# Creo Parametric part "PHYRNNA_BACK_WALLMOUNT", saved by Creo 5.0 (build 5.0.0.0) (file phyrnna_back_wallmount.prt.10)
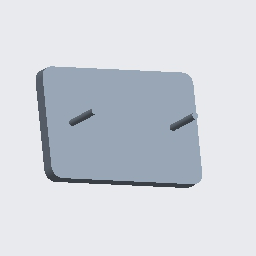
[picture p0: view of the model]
Units: Inch lbm Second (Pro/E Default); INCH, POUND, SECS

Created from: INLBS_PART_SOLID.PRT

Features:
  1. datum plane "RIGHT"
  2. datum plane "TOP"
  3. datum plane "FRONT"
  4. coordinate system
  5. sketch "Sketch 1"
  6. extrusion "Extrude 1"
  7. sketch "Sketch 2"
  8. extrusion "Extrude 2"
  9. sketch "Sketch 1", "A_3"
  10. extruded cut "Extrude 1"
  11. chamfer "Chamfer 1"
  12. sketch "Sketch 2"
  13. extruded cut "Extrude 2"

Other named items: BASE_S, BASE_E, PEG_S, PEG_E, NOTCH_S, NOTCH_E, NOTCH_C, GROOVE_S, GROOVE_E

Surfaces: 14 plane, 6 cylinder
